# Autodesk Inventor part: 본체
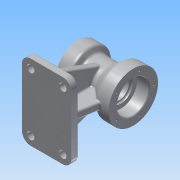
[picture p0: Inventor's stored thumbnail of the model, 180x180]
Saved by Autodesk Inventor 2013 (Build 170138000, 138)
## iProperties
Created: 2015-08
Part Number: 본체
Material: 알루미늄 6061
Document SubType Name: Modeling
Designer: ST3
Density: 2.71 g/cm^3
Mass: 1076.88 g
Surface Area: 747.39 cm^2
Volume: 397.374 cm^3
Author: ST3
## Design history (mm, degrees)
sketch "스케치1"
  geometry: L1 (0, 0)-(35.699, 0); L2 (-45, 35)-(-25, 35); L3 (-25, 35)-(-19.804, 26); L4 (-19.804, 26)-(8.315, 26); L5 (8.315, 26)-(25, 40); L6 (25, 40)-(45, 40); L7 (45, 40)-(45, 26); L8 (22, 16)-(-28, 16); L9 (-45, 20)-(-45, 35); L10 (0, 0)-(0, -43.803); L11 (-45, 20)-(-28, 20); L12 (-28, 20)-(-28, 16); L13 (45, 26)-(25, 26); L14 (25, 26)-(25, 19); L15 (25, 19)-(22, 19); L16 (22, 19)-(22, 16)
  constraints: 32 end point, 9 parallel, 4 perpendicular, 1 horizontal
  dimensions: "d4" = 20 distance of L2.start L2.end; "d5" = 20 distance of L5.end L6.end; "d7" = 40 deg angle of L4 L5; "d15" = 90 distance between parallel lines of L7 L9; "d17" = 32 diameter of L8 L1; "d18" = 80 diameter of L6 L1; "d19" = 70 diameter of L2 L1; "d23" = 52 diameter of L4 L1; "d112" = 40 diameter of L11 L1; "d113" = 52 diameter of L13 L1; "d114" = 38 diameter of L15 L1; "d115" = 3 distance of L14.end L15.end; "d116" = 60 deg angle of L4 L3; "d159" = 17 distance of L9.start L11.end; "d160" = 20 distance of L7.end L13.end
revolve "회전1" sketch "스케치1" stored, may be unused: angle "d28" = 90 deg
node "작업 평면1"
sketch "스케치2"
  geometry: L1 (-45, -35)-(-25, -35) reference; L2 (25, -40)-(45, -40) reference; L3 (-45, -90)-(-45, -78); L4 (-45, -78)-(35, -78); L5 (35, -78)-(35, -90); L6 (-45, -35)-(-45, 35) reference; L7 (-45, -90)-(35, -90); 1 further point
  constraints: 8 end point, 1 parallel, 1 perpendicular
  dimensions: "d34" = 0 distance between parallel lines of L6 L3; "d36" = 90 distance from line of point (0, 0) L7; "d37" = 80 distance of L3.end L4.end; "d38" = 12 distance of L4.end L5.end
extrude "돌출1" join sketch "스케치2" stored distance "d39" = 122; taper "d40" = 0 deg
node "작업 평면2"
sketch "스케치4"
  geometry: L1 (-45, -78)-(35, -78) reference; L2 (-45, -90)-(-45, -78) reference; L3 (-45, -78)-(35, -78) reference; L4 (35, -78)-(35, -90) reference; L5 (35, -90)-(-45, -90) reference; L6 (-45, -35)-(-25, -35) reference; L7 (-19.804, -26)-(8.315, -26) reference; L8 (25, -40)-(45, -40) reference; L9 (-25, -35)-(-19.804, -26) reference; L10 (8.315, -26)-(25, -40) reference; L11 (-35, -78)-(-35, -35); L12 (25, -78)-(31.7, -40); L13 (-35, -35)-(-35, -25.572); L14 (-35, -25.572)-(31.7, -26); L15 (31.7, -40)-(32.614, -34.816); L16 (32.614, -34.816)-(31.7, -26); 1 further point
  constraints: 12 end point, 4 point on line, 2 collinear, 1 midpoint, 1 perpendicular
  dimensions: "d42" = 10 distance between parallel lines of L11 L2; "d44" = 80 deg angle of L1 L12; "d45" = 10 distance of L1.end L12.start
extrude "돌출2" join sketch "스케치4" stored distance "d46" = 12; taper "d47" = 0 deg
sketch "스케치5"
  geometry: L1 (28.973, 0)-(0, 0) reference; 3 further points
  constraints: 3 other
extrude "돌출3" join sketch "스케치5" stored distance "d48" = 12; taper "d49" = 0 deg
sketch "스케치6"
  geometry: L1 (0, 0)-(28.973, 0) reference; 3 further points
  constraints: 3 other
extrude "돌출4" join sketch "스케치6" stored distance "d50" = 12; taper "d51" = 0 deg
node "작업 평면3"
sketch "스케치7"
  geometry: L1 (0, 12)-(122, 12) reference; L2 (10, 12)-(35.909, 83.185); L3 (112, 12)-(86.091, 83.185); A1 r 26 centre (61, 90) between (67, 64.702) and (55, 64.702) reference; 1 further point
  constraints: 4 end point, 2 point on circle, 2 point on line
  dimensions: "d52" = 10 distance of L1.start L2.start; "d53" = 70 deg angle of L1 L2; "d54" = 10 distance of L1.end L3.start; "d55" = 70 deg angle of L1 L3
extrude "돌출5" join sketch "스케치7" stored distance "d56" = 12; taper "d57" = 0 deg
fillet "모깎기1" dims "d82" = 5
sketch "스케치10"
  geometry: L1 (67, 12)-(67, 64.702) reference; L2 (112, 12)-(67, 12) reference; L3 (112, 12)-(86.091, 83.185) reference; L4 (4.674, 30)-(120.153, 30); L5 (37, 40.448)-(37, 24); L6 (85, 38.314)-(85, 25.447); L7 (0, 12)-(122, 12) reference; L8 (61, 12)-(61, 38.306); L9 (31, 30)-(31, 36); L10 (43, 30)-(43, 36); L11 (79, 30)-(79, 37.447); L12 (91, 30)-(91, 37.447); L13 (37, 42)-(44.916, 42); L14 (85, 43.447)-(79, 43.447); A1 r 26 centre (61, 90) between (67, 64.702) and (86.091, 83.185) reference; A2 r 6 centre (37, 30) between (31, 30) and (43, 30); A3 r 6 centre (85, 30) between (79, 30) and (91, 30); A4 r 6 centre (37, 36) between (31, 36) and (43, 36); A5 r 6 centre (85, 37.447) between (79, 37.447) and (79, 37.447)
  constraints: 20 end point, 12 point on circle, 11 point on line, 6 tangent, 4 centre point, 4 parallel, 4 perpendicular, 1 midpoint
  dimensions: "d83" = 18 distance between parallel lines of L2 L4; "d84" = 24 distance between parallel lines of L5 L8; "d85" = 48 distance between parallel lines of L5 L6; "d86" = 12 diameter of A2; "d87" = 12 diameter of A3; "d88" = 12 diameter of A4; "d89" = 12 diameter of A5; "d91" = 18 distance from line of L6.end L14; "d92" = 18 distance of L13.start L5.end
extrude "돌출6" cut sketch "스케치10" stored distance "d93" = 12; taper "d94" = 0 deg
node "작업 평면4"
fillet "모깎기2" dims "d95" = 3
fillet "모깎기3" dims "d96" = 3
fillet "모깎기4" dims "d97" = 14
sketch "스케치11"
  geometry: C1 r 6 at (0, 108); C2 r 6 at (52, 108); C3 r 6 at (0, 14); C4 r 6 at (52, 14); A1 r 14 centre (0, 14) between (-14, 14) and (0, 0) reference; A2 r 14 centre (52, 14) between (52, 0) and (66, 14) reference; A3 r 14 centre (52, 108) between (66, 108) and (52, 122) reference; A4 r 14 centre (0, 108) between (0, 122) and (-14, 108) reference; 1 further point
  constraints: 4 centre point, 4 coincident
  dimensions: "d100" = 12 diameter of C3; "d101" = 12 diameter of C1; "d102" = 12 diameter of C2; "d103" = 12 diameter of C4
extrude "돌출7" cut sketch "스케치11" stored distance "d104" = 12; taper "d105" = 0 deg
sketch "스케치12"
  geometry: C1 r 16 at (0, 0) reference
extrude "돌출8" cut sketch "스케치12" stored distance "d106" = 12; taper "d107" = 0 deg
sketch "스케치13"
  geometry: C1 r 20 at (0, 0) reference
extrude "돌출9" cut sketch "스케치13" stored distance "d109" = 12; taper "d110" = 0 deg
sketch "스케치14" dims "d117" = 66
  geometry: C1 r 40 at (0, 0) reference; C2 r 2.189 at (0, 33); 1 further point
  constraints: 1 centre point, 1 coincident, 1 vertical alignment, 2 other
hole "구멍3" sketch "스케치14" at (0, 33) diameter "d119" = 3.242; stored, may be unused: countersink angle "d123" = 90 deg, drill point angle "d125" = 118 deg; dims "d120" = 10, "d121" = 4, "d122" = 2, "d124" = 13
sketch "스케치15" dims "d129" = 54
  geometry: C1 r 20 at (0, 0) reference; C2 r 2.341 at (0, 27); 1 further point
  constraints: 1 centre point, 1 coincident, 1 vertical alignment, 2 other
hole "구멍4" sketch "스케치15" at (0, 27) diameter "d131" = 3.242; stored, may be unused: countersink angle "d135" = 90 deg, drill point angle "d137" = 118 deg; dims "d132" = 10, "d133" = 4, "d134" = 2, "d136" = 13
fillet "모깎기5" dims "d141" = 3
fillet "모깎기6" dims "d142" = 0.3
chamfer "모따기1" distance "d143" = 1; stored, may be unused: second distance "d144" = 2, angle "d145" = 45 deg
chamfer "모따기2" distance "d146" = 1; stored, may be unused: second distance "d147" = 2, angle "d148" = 45 deg
fillet "모깎기7" dims "d149" = 3
fillet "모깎기8" dims "d150" = 3
fillet "모깎기9" dims "d151" = 3
fillet "모깎기10" dims "d152" = 3
sketch "스케치16"
  geometry: L1 (-35, -37.881)-(-35, -75) reference; L2 (21, -78)-(-31, -78) reference; L3 (-35, -54)-(-19, -54); L4 (-19, -54)-(-19, -65.099); L5 (-22.002, -74.739)-(-22.002, -33.261); L6 (-22.002, -33.261)-(-15.998, -33.261); L7 (-15.998, -33.261)-(-15.998, -74.739); L8 (-15.998, -74.739)-(-22.002, -74.739); L9 (-22.002, -74.739)-(-15.998, -33.261); L10 (-22.002, -33.261)-(-15.998, -74.739); L11 (-19, -54)-(-31.507, -54); 1 further point
  constraints: 10 end point, 2 parallel, 1 midpoint, 1 perpendicular, 1 point on line, 2 other
  dimensions: "d153" = 24 distance between parallel lines of L2 L3; "d154" = 16 distance between parallel lines of L1 L4; "d155" = 0 distance of L3.end L11.start; "d156" = 0 distance of L3.end L11.start
extrude "돌출10" join sketch "스케치16" distance "d157" = 0.5; taper "d158" = 0 deg
node "솔리드1"
mirror "대칭1"
pattern_circular "원형 패턴3" dims angle "d127" = 360 deg
pattern_circular "원형 패턴4" dims angle "d139" = 360 deg
node "투영된 루프1"
node "투영된 루프2"
other parameters: "d29" = 0, "d41" = 0
